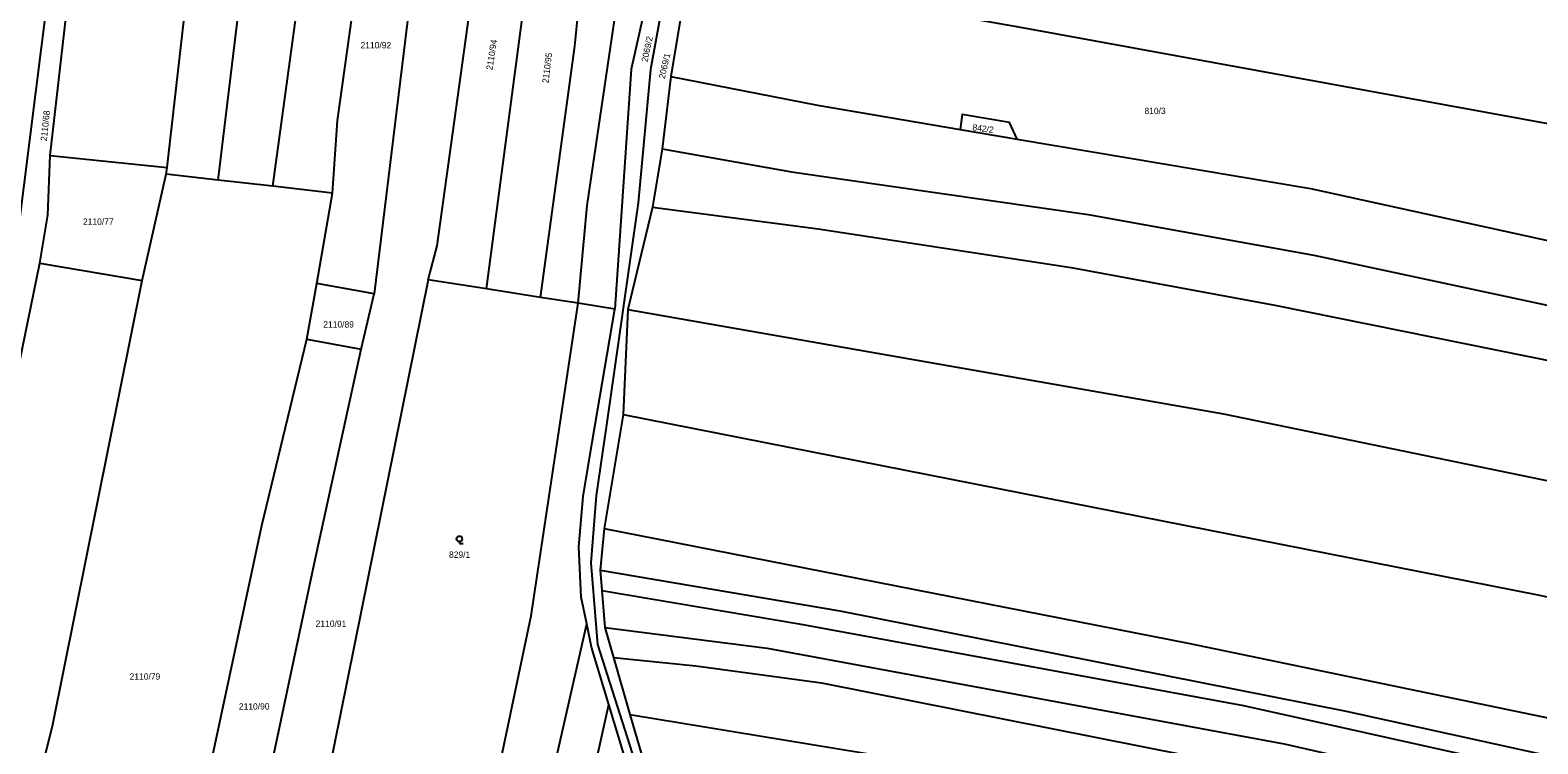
# Model space of a CAD drawing. Extents: x -776734 to -748832, y -1118122 to -976986.
# Drawn here: x -752783.6 to -752379, y -1113980.3 to -1113788.6 of the extents above; entities that cross this region are included whole.
import ezdxf

# ---------------------------------------------------------------- set-up
doc = ezdxf.new("R2010")
doc.units = 0
for name, color, linetype in [('KM_Hranice obce', 7, 'Continuous'), ('KM_Hranice parcel', 7, 'Continuous'), ('KM_Parcelní čísla', 7, 'Continuous'), ('KM_Značky kultur', 7, 'Continuous')]:
    doc.layers.add(name, color=color, linetype=linetype)

msp = doc.modelspace()

# ---------------------------------------------------------------- linework, layer by layer
at = {"layer": 'KM_Hranice obce'}
for p, q in [((-752676.83, -1113855.64), (-752704.28, -1113991.81)), ((-752676.83, -1113855.64), (-752704.28, -1113991.81)), ((-752661.18, -1113858.08), (-752676.83, -1113855.64)), ((-752661.18, -1113858.08), (-752676.83, -1113855.64)), ((-752646.69, -1113860.35), (-752661.18, -1113858.08)), ((-752646.69, -1113860.35), (-752661.18, -1113858.08)), ((-752636.58, -1113861.93), (-752646.69, -1113860.35)), ((-752636.58, -1113861.93), (-752646.69, -1113860.35)), ((-752626.68, -1113863.55), (-752636.58, -1113861.93)), ((-752626.68, -1113863.55), (-752636.58, -1113861.93)), ((-752632.76, -1113899.24), (-752626.68, -1113863.55)), ((-752632.76, -1113899.24), (-752626.68, -1113863.55)), ((-752624.32, -1113982.98), (-752628.32, -1113969.72)), ((-752624.32, -1113982.98), (-752628.32, -1113969.72))]:
    msp.add_line(p, q, dxfattribs=at)
for points in [[(-752634.26, -1113948.04), (-752635.74, -1113940.9), (-752636.34, -1113927.31), (-752635.18, -1113913.86), (-752632.76, -1113899.24)], [(-752634.26, -1113948.04), (-752635.74, -1113940.9), (-752636.34, -1113927.31), (-752635.18, -1113913.86), (-752632.76, -1113899.24)], [(-752628.32, -1113969.72), (-752632.97, -1113954.31), (-752634.26, -1113948.04)], [(-752628.32, -1113969.72), (-752632.97, -1113954.31), (-752634.26, -1113948.04)]]:
    msp.add_lwpolyline(points, dxfattribs=at)
at = {"layer": 'KM_Hranice parcel'}
for p, q in [((-752661.18, -1113858.08), (-752645.52, -1113739.69)), ((-752677.86, -1113749.54), (-752691.28, -1113859.45)), ((-752606.93, -1113772.17), (-752611.72, -1113801.02)), ((-752611.72, -1113801.02), (-752613.96, -1113820.43)), ((-752534.02, -1113815.25), (-752518.7, -1113817.84)), ((-752613.96, -1113820.43), (-752616.64, -1113836.16)), ((-752778.22, -1113822.25), (-752746.87, -1113825.51)), ((-752753.57, -1113855.83), (-752747.1, -1113827.25)), ((-752747.1, -1113827.25), (-752746.87, -1113825.51)), ((-752733.15, -1113828.84), (-752747.1, -1113827.25)), ((-752718.51, -1113830.5), (-752733.15, -1113828.84)), ((-752702.42, -1113832.33), (-752718.51, -1113830.5)), ((-752706.66, -1113856.6), (-752702.42, -1113832.33)), ((-752616.64, -1113836.16), (-752623.23, -1113863.58)), ((-752781.04, -1113851.17), (-752753.57, -1113855.83)), ((-752709.34, -1113871.56), (-752706.66, -1113856.6)), ((-752691.28, -1113859.45), (-752706.66, -1113856.6)), ((-752694.73, -1113874.23), (-752691.28, -1113859.45)), ((-752623.23, -1113863.58), (-752624.51, -1113891.78)), ((-752709.34, -1113871.56), (-752694.73, -1113874.23)), ((-752624.51, -1113891.78), (-752629.59, -1113922.43)), ((-752629.59, -1113922.43), (-752630.66, -1113933.61)), ((-752630.66, -1113933.61), (-752630.23, -1113939.07)), ((-752630.23, -1113939.07), (-752629.41, -1113948.98)), ((-752629.41, -1113948.98), (-752627.08, -1113957.06)), ((-752627.08, -1113957.06), (-752622.66, -1113972.37)), ((-752622.66, -1113972.37), (-752499.87, -1113992.53)), ((-752622.66, -1113972.37), (-752617.37, -1113990.44))]:
    msp.add_line(p, q, dxfattribs=at)
for points in [[(-752718.51, -1113830.5), (-752706.79, -1113744.62), (-752687.31, -1113618.79), (-752672.38, -1113554.21), (-752661.85, -1113512.96), (-752635.33, -1113443.56), (-752621.49, -1113402.45), (-752592.43, -1113335.56)], [(-752485.85, -1113340.9), (-752491.92, -1113351.43), (-752501.09, -1113372.33), (-752506.44, -1113387.58), (-752519.72, -1113431.54), (-752533.47, -1113464.18), (-752547.99, -1113491.95), (-752554.34, -1113509.05), (-752559.32, -1113524.35), (-752564, -1113540.05), (-752572.39, -1113570.1), (-752587.23, -1113633.34), (-752590.04, -1113652.41), (-752594.15, -1113682.21), (-752603.51, -1113724.72), (-752617.16, -1113799.14), (-752620.48, -1113835), (-752628.97, -1113894.58), (-752631.7, -1113913.55), (-752633.16, -1113931.63), (-752631.31, -1113953.54), (-752610.14, -1114020.09)], [(-752636.58, -1113861.93), (-752634.11, -1113835.66), (-752614.58, -1113702.84), (-752607.08, -1113657.8)], [(-752593.53, -1113659.89), (-752595.97, -1113676.87), (-752607.14, -1113731.15), (-752622.35, -1113799.07), (-752626.68, -1113863.55)], [(-752746.87, -1113825.51), (-752738.98, -1113756.21), (-752726.51, -1113673.45)], [(-752733.15, -1113828.84), (-752725.61, -1113766.64), (-752711.93, -1113680.98)], [(-752837.26, -1114067.71), (-752816.91, -1113989.3), (-752799.76, -1113913.36), (-752786.79, -1113843.06), (-752778.9, -1113780.39), (-752766.72, -1113694.52)], [(-752778.22, -1113822.25), (-752772.47, -1113772.12), (-752759.79, -1113691.77)], [(-752702.42, -1113832.33), (-752701.15, -1113812.85), (-752688.09, -1113719.46)], [(-752646.69, -1113860.35), (-752637.4, -1113792.93), (-752632.3, -1113741.8)], [(-752676.83, -1113855.64), (-752674.4, -1113846.55), (-752661.22, -1113751.5)], [(-752362.05, -1113816.32), (-752518.3, -1113787.8), (-752606.93, -1113772.17)], [(-752611.72, -1113801.02), (-752572.31, -1113808.78), (-752534.02, -1113815.25)], [(-752518.7, -1113817.84), (-752520.8, -1113813.38), (-752533.52, -1113811.24), (-752534.02, -1113815.25)], [(-752613.96, -1113820.43), (-752579.28, -1113826.6), (-752499.65, -1113838.1), (-752439.16, -1113849.06), (-752247.55, -1113890.09), (-752114.51, -1113915.08), (-752012.56, -1113935.61), (-751947.95, -1113950.01), (-751894.35, -1113963.98)], [(-752518.7, -1113817.84), (-752440.03, -1113831.15), (-752329.9, -1113855.26)], [(-752781.04, -1113851.17), (-752778.81, -1113838.3), (-752778.22, -1113822.25)], [(-752616.64, -1113836.16), (-752572.16, -1113841.95), (-752504.23, -1113852.37), (-752449.63, -1113862.47), (-752254.42, -1113901.89), (-752137.26, -1113926.63), (-752072.06, -1113937.07), (-751990.72, -1113955.7), (-751912.21, -1113975.14)], [(-752829.59, -1114071.21), (-752798.28, -1113935.15), (-752781.04, -1113851.17)], [(-752804.37, -1114082.79), (-752777.52, -1113975.02), (-752753.57, -1113855.83)], [(-752660.17, -1113998.22), (-752649.17, -1113945.86), (-752636.58, -1113861.93)], [(-752623.23, -1113863.58), (-752463.39, -1113891.64), (-752195.83, -1113946.9), (-752102.76, -1113962.49), (-752093.41, -1113965.75), (-752006.07, -1113982.13), (-751949.55, -1113999.64)], [(-752760.57, -1114105.09), (-752721.44, -1113921.63), (-752709.34, -1113871.56)], [(-752745.34, -1114119.12), (-752741.5, -1114092.87), (-752707.4, -1113931.98), (-752694.73, -1113874.23)], [(-752624.51, -1113891.78), (-752379.07, -1113940.23), (-752239.16, -1113970.34), (-752037.75, -1114006.93), (-751983.81, -1114022.61)], [(-752629.59, -1113922.43), (-752472.89, -1113953.22), (-752359.12, -1113976.87), (-752217.56, -1114005.39), (-752097.15, -1114027.52), (-752044.22, -1114039.33), (-752018.55, -1114047.53)], [(-752630.66, -1113933.61), (-752566.34, -1113944.53), (-752430.46, -1113971.47), (-752362.48, -1113986.39), (-752194.01, -1114019.32), (-752089.77, -1114038.86), (-752064.32, -1114044.21), (-752027.89, -1114054.72)], [(-752630.23, -1113939.07), (-752577.28, -1113947.98), (-752458.02, -1113969.96), (-752363.58, -1113990.99), (-752099.79, -1114043.47), (-752059.67, -1114052.82), (-752034.68, -1114059.94)], [(-752678.87, -1114140.59), (-752672.75, -1114117.71), (-752634.26, -1113948.04)], [(-752629.41, -1113948.98), (-752585.83, -1113954.56), (-752447.12, -1113980.26), (-752366.49, -1113998.56), (-752302.62, -1114009.92), (-752091.61, -1114053.03), (-752041.07, -1114064.86)], [(-752627.08, -1113957.06), (-752604.93, -1113959.33), (-752571.28, -1113963.89), (-752412.19, -1113995.48), (-752207.66, -1114037.55), (-752102.65, -1114057.53), (-752047.85, -1114070.07)], [(-752669.79, -1114141.43), (-752661.32, -1114105.94), (-752638.63, -1114015.99), (-752628.32, -1113969.72)]]:
    msp.add_lwpolyline(points, dxfattribs=at)
at = {"layer": 'KM_Značky kultur'}
for p, q in [((-752668.42, -1113925.952), (-752668.42, -1113926.45)), ((-752668.42, -1113926.45), (-752667.419, -1113926.45))]:
    msp.add_line(p, q, dxfattribs=at)
msp.add_circle((-752668.4193, -1113925.2009), 0.75, dxfattribs=at)

# ---------------------------------------------------------------- texts
at = {"layer": 'KM_Parcelní čísla'}
for s, p in [('2110/92', (-752694.936, -1113793.49)), ('810/3', (-752484.588, -1113811.14)), ('2110/77', (-752769.416, -1113840.87)), ('2110/89', (-752704.936, -1113868.46)), ('829/1', (-752671.19, -1113930.3)), ('2110/91', (-752706.986, -1113948.84)), ('2110/79', (-752756.896, -1113963.02)), ('2110/90', (-752727.576, -1113971.05))]:
    msp.add_text(s, height=1.7, dxfattribs=at).set_placement(p)
for s, rotation, p in [('2110/94', 81, (-752659.559, -1113799.403)), ('2069/2', 78, (-752617.929, -1113797.278)), ('2110/95', 83, (-752644.516, -1113802.906)), ('2069/1', 77, (-752613.319, -1113801.767)), ('2110/68', 84, (-752779.125, -1113818.45)), ('842/2', 351.999997, (-752530.814, -1113815.472))]:
    msp.add_text(s, height=1.7, rotation=rotation, dxfattribs=at).set_placement(p)

doc.saveas('drawing.dxf')
